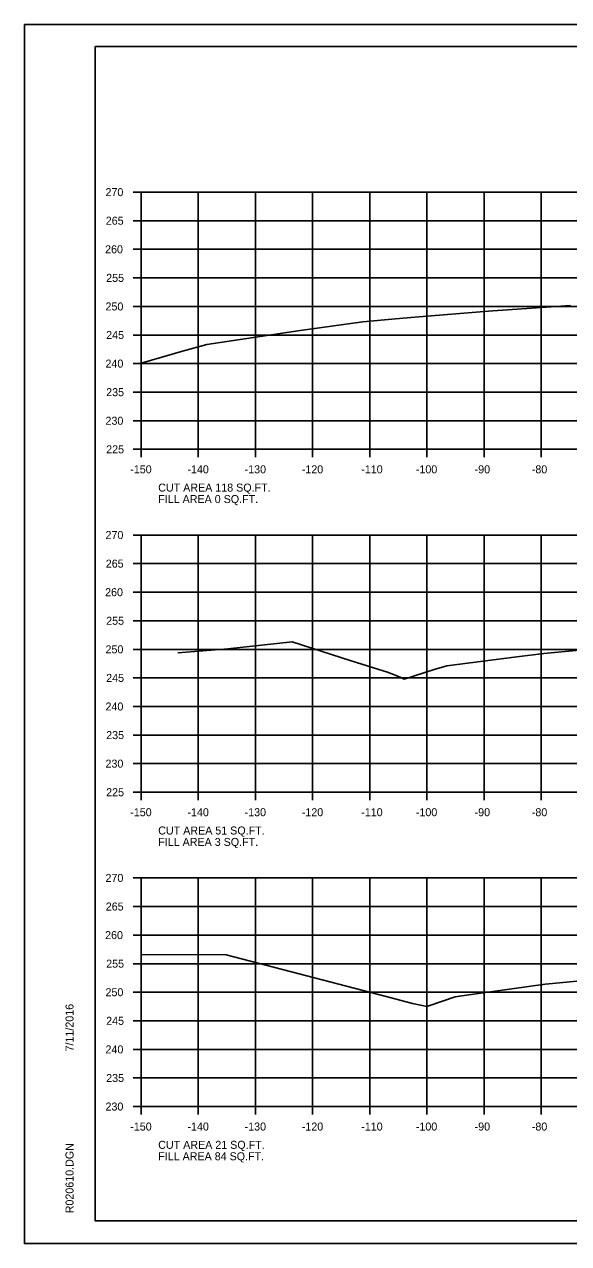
# Model space of a CAD drawing. Extents: x 1103485 to 1107180, y 2010593 to 2011873.
# Drawn here: x 1106846.8 to 1106942, y 2011446.2 to 2011659.5 of the extents above; entities that cross this region are included whole.
import ezdxf

# ---------------------------------------------------------------- set-up
doc = ezdxf.new("R2010")
doc.units = 0
for name, color, linetype in [('R_Axis', 7, 'Continuous'), ('R_Axis Annot', 7, 'Continuous'), ('R_Border', 7, 'Continuous'), ('R_Exist Surface', 7, 'Continuous'), ('R_Grid', 7, 'Continuous'), ('R_No Plot', 7, 'Continuous')]:
    doc.layers.add(name, color=color, linetype=linetype)

msp = doc.modelspace()

# ---------------------------------------------------------------- linework, layer by layer
at = {"layer": 'R_Axis'}
for p, q in [((1106865.78, 2011630.17), (1106867.18, 2011630.17)), ((1106867.18, 2011585.17), (1106867.18, 2011630.17)), ((1106865.78, 2011625.17), (1106867.18, 2011625.17)), ((1106865.78, 2011620.17), (1106867.18, 2011620.17)), ((1106865.78, 2011615.17), (1106867.18, 2011615.17)), ((1106865.78, 2011610.17), (1106867.18, 2011610.17)), ((1106865.78, 2011605.17), (1106867.18, 2011605.17)), ((1106865.78, 2011600.17), (1106867.18, 2011600.17)), ((1106865.78, 2011595.17), (1106867.18, 2011595.17)), ((1106865.78, 2011590.17), (1106867.18, 2011590.17)), ((1106865.78, 2011585.17), (1106867.18, 2011585.17)), ((1106867.18, 2011585.17), (1107167.18, 2011585.17)), ((1106867.18, 2011583.77), (1106867.18, 2011585.17)), ((1106877.18, 2011583.77), (1106877.18, 2011585.17)), ((1106887.18, 2011583.77), (1106887.18, 2011585.17)), ((1106897.18, 2011583.77), (1106897.18, 2011585.17)), ((1106907.18, 2011583.77), (1106907.18, 2011585.17)), ((1106917.18, 2011583.77), (1106917.18, 2011585.17)), ((1106927.18, 2011583.77), (1106927.18, 2011585.17)), ((1106937.18, 2011583.77), (1106937.18, 2011585.17)), ((1106865.78, 2011570.17), (1106867.18, 2011570.17)), ((1106867.18, 2011525.17), (1106867.18, 2011570.17)), ((1106865.78, 2011565.17), (1106867.18, 2011565.17)), ((1106865.78, 2011560.17), (1106867.18, 2011560.17)), ((1106865.78, 2011555.17), (1106867.18, 2011555.17)), ((1106865.78, 2011550.17), (1106867.18, 2011550.17)), ((1106865.78, 2011545.17), (1106867.18, 2011545.17)), ((1106865.78, 2011540.17), (1106867.18, 2011540.17)), ((1106865.78, 2011535.17), (1106867.18, 2011535.17)), ((1106865.78, 2011530.17), (1106867.18, 2011530.17)), ((1106865.78, 2011525.17), (1106867.18, 2011525.17)), ((1106867.18, 2011525.17), (1107167.18, 2011525.17)), ((1106867.18, 2011523.77), (1106867.18, 2011525.17)), ((1106877.18, 2011523.77), (1106877.18, 2011525.17)), ((1106887.18, 2011523.77), (1106887.18, 2011525.17)), ((1106897.18, 2011523.77), (1106897.18, 2011525.17)), ((1106907.18, 2011523.77), (1106907.18, 2011525.17)), ((1106917.18, 2011523.77), (1106917.18, 2011525.17)), ((1106927.18, 2011523.77), (1106927.18, 2011525.17)), ((1106937.18, 2011523.77), (1106937.18, 2011525.17)), ((1106865.78, 2011510.17), (1106867.18, 2011510.17)), ((1106867.18, 2011470.17), (1106867.18, 2011510.17)), ((1106865.78, 2011505.17), (1106867.18, 2011505.17)), ((1106865.78, 2011500.17), (1106867.18, 2011500.17)), ((1106865.78, 2011495.17), (1106867.18, 2011495.17)), ((1106865.78, 2011490.17), (1106867.18, 2011490.17)), ((1106865.78, 2011485.17), (1106867.18, 2011485.17)), ((1106865.78, 2011480.17), (1106867.18, 2011480.17)), ((1106865.78, 2011475.17), (1106867.18, 2011475.17)), ((1106865.78, 2011470.17), (1106867.18, 2011470.17)), ((1106867.18, 2011470.17), (1107167.18, 2011470.17)), ((1106867.18, 2011468.77), (1106867.18, 2011470.17)), ((1106877.18, 2011468.77), (1106877.18, 2011470.17)), ((1106887.18, 2011468.77), (1106887.18, 2011470.17)), ((1106897.18, 2011468.77), (1106897.18, 2011470.17)), ((1106907.18, 2011468.77), (1106907.18, 2011470.17)), ((1106917.18, 2011468.77), (1106917.18, 2011470.17)), ((1106927.18, 2011468.77), (1106927.18, 2011470.17)), ((1106937.18, 2011468.77), (1106937.18, 2011470.17))]:
    msp.add_line(p, q, dxfattribs=at)
at = {"layer": 'R_Border'}
for p, q in [((1106859.18, 2011655.63), (1107175.36, 2011655.63)), ((1106859.18, 2011450.17), (1106859.18, 2011655.63)), ((1106859.18, 2011450.17), (1106859.18, 2011450.17)), ((1107175.36, 2011450.17), (1106859.18, 2011450.17))]:
    msp.add_line(p, q, dxfattribs=at)
at = {"layer": 'R_Exist Surface'}
for points in [[(1106867.18, 2011600.22), (1106874.44, 2011602.33), (1106878.67, 2011603.52), (1106895.03, 2011605.97), (1106905.98, 2011607.5), (1106911.71, 2011608), (1106915.09, 2011608.32), (1106927.94, 2011609.32), (1106928.72, 2011609.38), (1106942.28, 2011610.31)], [(1106873.62, 2011549.58), (1106882.35, 2011550.27), (1106893.58, 2011551.46), (1106903.92, 2011548.16), (1106910.43, 2011546.12), (1106912.64, 2011545.22), (1106913.2, 2011544.95), (1106918.45, 2011546.65), (1106920.67, 2011547.28), (1106932.91, 2011548.86), (1106937.63, 2011549.46), (1106943.86, 2011550.04)], [(1106867.18, 2011496.76), (1106882.05, 2011496.72), (1106910.05, 2011489.43), (1106914.64, 2011488.19), (1106914.92, 2011488.14), (1106917.18, 2011487.69), (1106917.52, 2011487.79), (1106922.11, 2011489.37), (1106923.31, 2011489.54), (1106937.88, 2011491.58), (1106939.12, 2011491.7), (1106946.43, 2011492.39)]]:
    msp.add_lwpolyline(points, dxfattribs=at)
at = {"layer": 'R_Grid'}
for p, q in [((1106867.18, 2011630.17), (1107167.18, 2011630.17)), ((1106867.18, 2011585.17), (1106867.18, 2011630.17)), ((1106877.18, 2011585.17), (1106877.18, 2011630.17)), ((1106887.18, 2011585.17), (1106887.18, 2011630.17)), ((1106897.18, 2011585.17), (1106897.18, 2011630.17)), ((1106907.18, 2011585.17), (1106907.18, 2011630.17)), ((1106917.18, 2011585.17), (1106917.18, 2011630.17)), ((1106927.18, 2011585.17), (1106927.18, 2011630.17)), ((1106937.18, 2011585.17), (1106937.18, 2011630.17)), ((1106867.18, 2011625.17), (1107167.18, 2011625.17)), ((1106867.18, 2011620.17), (1107167.18, 2011620.17)), ((1106867.18, 2011615.17), (1107167.18, 2011615.17)), ((1106867.18, 2011610.17), (1107167.18, 2011610.17)), ((1106867.18, 2011605.17), (1107167.18, 2011605.17)), ((1106867.18, 2011600.17), (1107167.18, 2011600.17)), ((1106867.18, 2011595.17), (1107167.18, 2011595.17)), ((1106867.18, 2011590.17), (1107167.18, 2011590.17)), ((1106867.18, 2011585.17), (1107167.18, 2011585.17)), ((1106867.18, 2011570.17), (1107167.18, 2011570.17)), ((1106867.18, 2011525.17), (1106867.18, 2011570.17)), ((1106877.18, 2011525.17), (1106877.18, 2011570.17)), ((1106887.18, 2011525.17), (1106887.18, 2011570.17)), ((1106897.18, 2011525.17), (1106897.18, 2011570.17)), ((1106907.18, 2011525.17), (1106907.18, 2011570.17)), ((1106917.18, 2011525.17), (1106917.18, 2011570.17)), ((1106927.18, 2011525.17), (1106927.18, 2011570.17)), ((1106937.18, 2011525.17), (1106937.18, 2011570.17)), ((1106867.18, 2011565.17), (1107167.18, 2011565.17)), ((1106867.18, 2011560.17), (1107167.18, 2011560.17)), ((1106867.18, 2011555.17), (1107167.18, 2011555.17)), ((1106867.18, 2011550.17), (1107167.18, 2011550.17)), ((1106867.18, 2011545.17), (1107167.18, 2011545.17)), ((1106867.18, 2011540.17), (1107167.18, 2011540.17)), ((1106867.18, 2011535.17), (1107167.18, 2011535.17)), ((1106867.18, 2011530.17), (1107167.18, 2011530.17)), ((1106867.18, 2011525.17), (1107167.18, 2011525.17)), ((1106867.18, 2011510.17), (1107167.18, 2011510.17)), ((1106867.18, 2011470.17), (1106867.18, 2011510.17)), ((1106877.18, 2011470.17), (1106877.18, 2011510.17)), ((1106887.18, 2011470.17), (1106887.18, 2011510.17)), ((1106897.18, 2011470.17), (1106897.18, 2011510.17)), ((1106907.18, 2011470.17), (1106907.18, 2011510.17)), ((1106917.18, 2011470.17), (1106917.18, 2011510.17)), ((1106927.18, 2011470.17), (1106927.18, 2011510.17)), ((1106937.18, 2011470.17), (1106937.18, 2011510.17)), ((1106867.18, 2011505.17), (1107167.18, 2011505.17)), ((1106867.18, 2011500.17), (1107167.18, 2011500.17)), ((1106867.18, 2011495.17), (1107167.18, 2011495.17)), ((1106867.18, 2011490.17), (1107167.18, 2011490.17)), ((1106867.18, 2011485.17), (1107167.18, 2011485.17)), ((1106867.18, 2011480.17), (1107167.18, 2011480.17)), ((1106867.18, 2011475.17), (1107167.18, 2011475.17)), ((1106867.18, 2011470.17), (1107167.18, 2011470.17))]:
    msp.add_line(p, q, dxfattribs=at)
at = {"layer": 'R_No Plot'}
for p, q in [((1106846.78, 2011659.52), (1107180.12, 2011659.52)), ((1106846.78, 2011446.19), (1107180.12, 2011446.19))]:
    msp.add_line(p, q, dxfattribs=at)
for points in [[(1106846.78, 2011659.52), (1107180.12, 2011659.52), (1107180.12, 2011446.19), (1106846.78, 2011446.19)], [(1107093.1, 2011655.63), (1107093.1, 2011645.75), (1107128.84, 2011645.75), (1107128.84, 2011642.83), (1107152.04, 2011642.83), (1107152.04, 2011618.5), (1107175.36, 2011618.5), (1107175.36, 2011450.17), (1106859.18, 2011450.17), (1106859.18, 2011655.63)]]:
    msp.add_lwpolyline(points, close=True, dxfattribs=at)

# ---------------------------------------------------------------- texts
at = {"layer": 'R_Axis Annot'}
for s, p in [('270', (1106860.96, 2011629.47)), ('265', (1106861.01, 2011624.47)), ('260', (1106860.89, 2011619.47)), ('255', (1106861.08, 2011614.47)), ('250', (1106860.96, 2011609.47)), ('245', (1106861.08, 2011604.47)), ('240', (1106860.96, 2011599.47)), ('235', (1106861.08, 2011594.47)), ('230', (1106860.96, 2011589.47)), ('225', (1106861.08, 2011584.47)), ('-150', (1106865.29, 2011580.97)), ('-140', (1106875.29, 2011580.97)), ('-130', (1106885.29, 2011580.97)), ('-120', (1106895.29, 2011580.97)), ('-110', (1106905.69, 2011580.97)), ('-100', (1106915.24, 2011580.97)), ('-90', (1106925.52, 2011580.97)), ('-80', (1106935.52, 2011580.97)), ('CUT AREA 118 SQ.FT.', (1106870.18, 2011577.77)), ('FILL AREA 0 SQ.FT.', (1106870.18, 2011575.77)), ('270', (1106860.96, 2011569.47)), ('265', (1106861.01, 2011564.47)), ('260', (1106860.89, 2011559.47)), ('255', (1106861.08, 2011554.47)), ('250', (1106860.96, 2011549.47)), ('245', (1106861.08, 2011544.47)), ('240', (1106860.96, 2011539.47)), ('235', (1106861.08, 2011534.47)), ('230', (1106860.96, 2011529.47)), ('225', (1106861.08, 2011524.47)), ('-150', (1106865.29, 2011520.97)), ('-140', (1106875.29, 2011520.97)), ('-130', (1106885.29, 2011520.97)), ('-120', (1106895.29, 2011520.97)), ('-110', (1106905.69, 2011520.97)), ('-100', (1106915.24, 2011520.97)), ('-90', (1106925.52, 2011520.97)), ('-80', (1106935.52, 2011520.97)), ('CUT AREA 51 SQ.FT.', (1106870.18, 2011517.77)), ('FILL AREA 3 SQ.FT.', (1106870.18, 2011515.77)), ('270', (1106860.96, 2011509.47)), ('265', (1106861.01, 2011504.47)), ('260', (1106860.89, 2011499.47)), ('255', (1106861.08, 2011494.47)), ('250', (1106860.96, 2011489.47)), ('245', (1106861.08, 2011484.47)), ('240', (1106860.96, 2011479.47)), ('235', (1106861.08, 2011474.47)), ('230', (1106860.96, 2011469.47)), ('-150', (1106865.29, 2011465.97)), ('-140', (1106875.29, 2011465.97)), ('-130', (1106885.29, 2011465.97)), ('-120', (1106895.29, 2011465.97)), ('-110', (1106905.69, 2011465.97)), ('-100', (1106915.24, 2011465.97)), ('-90', (1106925.52, 2011465.97)), ('-80', (1106935.52, 2011465.97)), ('CUT AREA 21 SQ.FT.', (1106870.18, 2011462.77)), ('FILL AREA 84 SQ.FT.', (1106870.18, 2011460.77))]:
    msp.add_text(s, height=1.4, dxfattribs=at).set_placement(p)
at = {"layer": 'R_Border'}
for s, p in [('7/11/2016', (1106855.37, 2011479.81)), ('R020610.DGN', (1106855.37, 2011451.49))]:
    msp.add_text(s, height=1.4, rotation=90, dxfattribs=at).set_placement(p)

doc.saveas('drawing.dxf')
